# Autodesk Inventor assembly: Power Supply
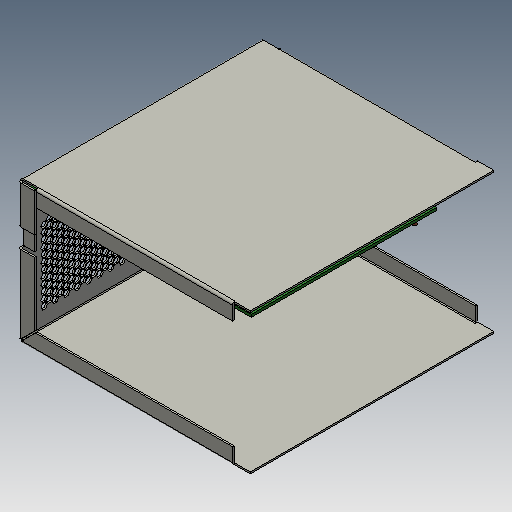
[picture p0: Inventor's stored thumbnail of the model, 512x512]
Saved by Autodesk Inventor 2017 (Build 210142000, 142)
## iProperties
Created: 2005-12
Part Number: Power Supply
Document SubType Name: Assembly
Designer: DanielSeverino
Author: DanielSeverino
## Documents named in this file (3)
- C:\Users\DanielSeverino\Desktop\01\Power Supply.iam
- C:\Users\DanielSeverino\Desktop\01\Top Casing.ipt
- C:\Users\DanielSeverino\Desktop\01\Power Supply PCB.ipt
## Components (2 placed, 2 different names)
1. Top Casing:1
2. Power Supply PCB:1
